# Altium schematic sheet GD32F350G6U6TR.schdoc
size 127 x 101 mm
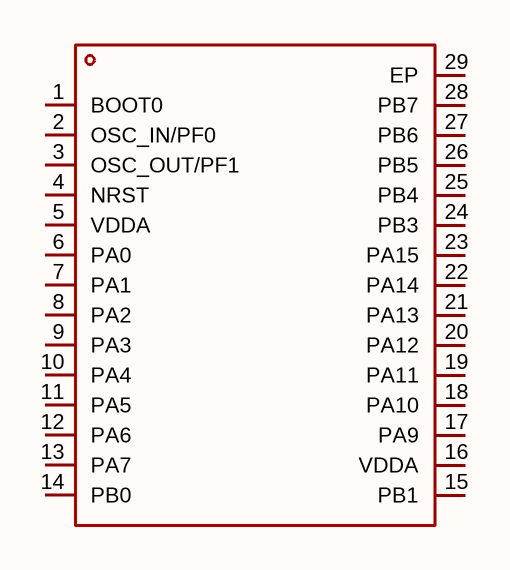
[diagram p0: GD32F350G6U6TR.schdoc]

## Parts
U?  gd32f350g6u6tr  [QFN-28_L4.0-W4.0-P0.40-BL-EP2.8]  (value not drawn)

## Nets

Not connected (* = marked no-connect by the designer): U? 1(BOOT0) 2(OSC_IN/PF0) 3(OSC_OUT/PF1) 4(NRST) 5(VDDA) 6(PA0) 7(PA1) 8(PA2) 9(PA3) 10(PA4) 11(PA5) 12(PA6) 13(PA7) 14(PB0) 15(PB1) 16(VDDA) 17(PA9) 18(PA10) 19(PA11) 20(PA12) 21(PA13) 22(PA14) 23(PA15) 24(PB3) 25(PB4) 26(PB5) 27(PB6) 28(PB7) 29(EP)

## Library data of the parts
U? = gd32f350g6u6tr: CPU内核:ARM Cortex-M4;CPU最大主频:108MHz;; Manufacturer: GigaDevice(兆易创新); AddInBom: yes; ModelId: ea8b28b44f5d42878c4615c9108a8123; ModelTransform: 157.48,157.48,0,0,0,0,0,0,0; CPU Maximum Speed: 108MHz; Program Storage Size: 32KB; Program Memory Type: FLASH; Number of I/O: 24; ADC (Bit): 12bit; Voltage - Supply: 2.6V~3.6V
